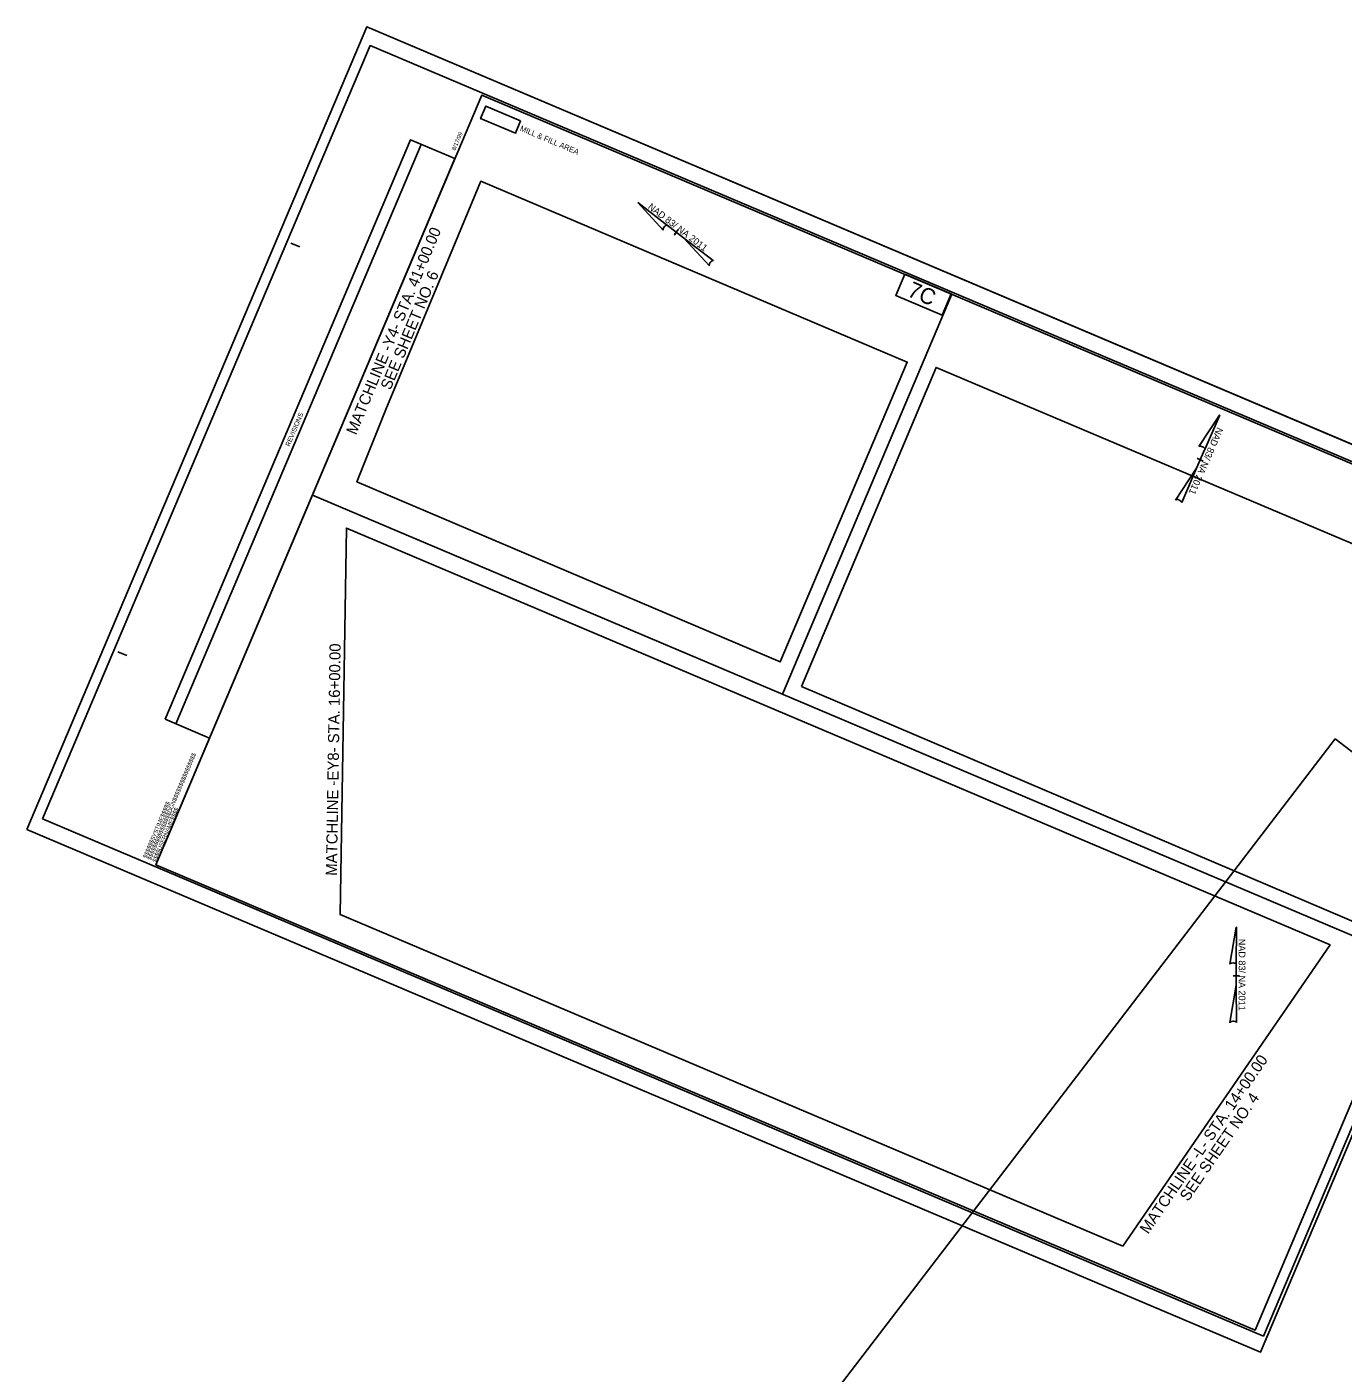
# Model space of a CAD drawing. Extents: x 1616919 to 1619754, y 897646 to 900286.
# Drawn here: x 1616919 to 1618573, y 898594 to 900286 of the extents above; entities that cross this region are included whole.
import ezdxf

# ---------------------------------------------------------------- set-up
doc = ezdxf.new("R2010")
doc.units = 0
for name, color, linetype in [('Exist DTM Breakline', 7, 'Continuous'), ('Exist DTM Breakline Underwater Cogo Number', 7, 'Continuous'), ('Exist DTM Breakline Underwater Cogo Point CELL', 7, 'Continuous'), ('Exist DTM Crownline', 7, 'Continuous'), ('Exist DTM Crownline Cogo Elevation', 7, 'Continuous'), ('Exist DTM Crownline Cogo Number', 7, 'Continuous'), ('Exist DTM Crownline Cogo Point CELL', 7, 'Continuous'), ('Exist DTM Regular Point CELL', 7, 'Continuous'), ('Exist DTM Top of Rail Cogo Number', 7, 'Continuous'), ('Exist DTM Top of Rail Cogo Point CELL', 7, 'Continuous'), ('Exist Railroads Signal Milepost CELL', 7, 'Continuous'), ('Exist Railroads Signal Milepost Cogo Elevation', 7, 'Continuous'), ('Exist Roads Curbs Cogo Point CELL', 7, 'Continuous'), ('Exist Roads EOP', 7, 'Continuous'), ('Exist Roads EOP Cogo Elevation', 7, 'Continuous'), ('Exist Roads EOT Cogo Number', 7, 'Continuous')]:
    doc.layers.add(name, color=color, linetype=linetype)

msp = doc.modelspace()

# ---------------------------------------------------------------- linework, layer by layer
at = {"layer": 'Exist DTM Breakline'}
msp.add_line((1617081, 899233), (1617081, 899233), dxfattribs=at)
at = {"layer": 'Exist DTM Breakline Underwater Cogo Number'}
msp.add_lwpolyline([(1618080.5, 899950), (1618022, 899974.8), (1618010.7, 899948.1), (1618069.2, 899923.3)], close=True, dxfattribs=at)
at = {"layer": 'Exist DTM Breakline Underwater Cogo Point CELL'}
for p, q in [((1617686.7, 900064.9), (1617686.6, 900064.9)), ((1617686.7, 900064.9), (1617686.6, 900064.9)), ((1617718.4, 900030.1), (1617686.6, 900064.9)), ((1617686.7, 900064.9), (1617724.5, 900035.8)), ((1617744.2, 900020.6), (1617723.4, 900036.6)), ((1617724.5, 900035.8), (1617723.5, 900036.6)), ((1617732.6, 900024.5), (1617732.5, 900024.5)), ((1617732.6, 900024.6), (1617737.5, 900030.9)), ((1617734.7, 900027.3), (1617732.6, 900024.5)), ((1617744.2, 900020.6), (1617776.5, 899985.2)), ((1617781.5, 899992), (1617744.2, 900020.6)), ((1618391.7, 899758.4), (1618417.7, 899797.7)), ((1618417.8, 899797.6), (1618398.7, 899753.8)), ((1618417.8, 899797.6), (1618417.7, 899797.7)), ((1618417.8, 899797.6), (1618417.7, 899797.7)), ((1618388.8, 899731.1), (1618399.3, 899755.1)), ((1618398.7, 899753.8), (1618399.2, 899755.1)), ((1618388.8, 899731.1), (1618362.3, 899691.1)), ((1618370.1, 899687.9), (1618388.8, 899731.1)), ((1618389.8, 899743.3), (1618389.7, 899743.3)), ((1618389.8, 899743.3), (1618397.1, 899740.1)), ((1618393, 899741.9), (1618389.8, 899743.3)), ((1618430.5, 899108.1), (1618438.7, 899154.4)), ((1618438.8, 899154.4), (1618438.7, 899154.4)), ((1618438.8, 899154.4), (1618438.7, 899154.4)), ((1618438.8, 899154.4), (1618438.7, 899106.6)), ((1618438.7, 899081.8), (1618438.7, 899108)), ((1618438.7, 899106.6), (1618438.7, 899108)), ((1618438.3, 899093.4), (1618434.7, 899093.4)), ((1618434.7, 899093.4), (1618434.7, 899093.4)), ((1618434.8, 899093.4), (1618442.8, 899093.4)), ((1618438.7, 899081.8), (1618430.4, 899034.6)), ((1618438.8, 899034.8), (1618438.7, 899081.8))]:
    msp.add_line(p, q, dxfattribs=at)
for centre, major_axis, start_param, end_param in [((1617721.3, 900033.1), (2.6, 3.33), 0.216388, 2.908219), ((1617779.3, 899988.5), (2.6, 3.33), 0.201328, 3.141593), ((1618395.3, 899756.3), (3.87, -1.72), 0.216388, 2.908219), ((1618366.1, 899689.3), (3.87, -1.72), 0.201328, 3.141593), ((1618434.6, 899107.6), (4.23, -0.03), 0.216388, 2.908219), ((1618434.6, 899034.4), (4.23, -0.03), 0.201328, 3.141593)]:
    msp.add_ellipse(centre, major_axis=major_axis, ratio=0.461098, start_param=start_param, end_param=end_param, dxfattribs=at)
at = {"layer": 'Exist DTM Crownline'}
msp.add_lwpolyline([(1617276, 899693.4), (1617090.8, 899256.1)], dxfattribs=at)
at = {"layer": 'Exist DTM Crownline Cogo Elevation'}
for p, q in [((1617346, 900285.5), (1616918.9, 899277.3)), ((1618896.2, 899628.9), (1617346, 900285.5)), ((1616918.9, 899277.3), (1618469.1, 898620.7))]:
    msp.add_line(p, q, dxfattribs=at)
at = {"layer": 'Exist DTM Crownline Cogo Number'}
msp.add_lwpolyline([(1618562.8, 899391.2), (1617924.4, 898557.6), (1619115.3, 897645.5), (1619625.1, 898311.3), (1619435.2, 898456.7), (1619563.8, 898624.6)], close=True, dxfattribs=at)
at = {"layer": 'Exist DTM Crownline Cogo Point CELL'}
msp.add_lwpolyline([(1616938.7, 899290.6), (1618472.8, 898640.8), (1618884.2, 899612.3), (1617350.2, 900262.1)], close=True, dxfattribs=at)
at = {"layer": 'Exist DTM Top of Rail Cogo Number'}
msp.add_lwpolyline([(1617539.3, 900167.5), (1617495.7, 900186), (1617489.1, 900170.4), (1617532.7, 900151.9)], close=True, dxfattribs=at)
at = {"layer": 'Exist DTM Top of Rail Cogo Point CELL'}
msp.add_lwpolyline([(1617539.3, 900167.5), (1617495.7, 900186), (1617489.1, 900170.4), (1617532.7, 900151.9), (1617539.3, 900167.5)], dxfattribs=at)
at = {"layer": 'Exist Railroads Signal Milepost CELL'}
for points in [[(1617369.9, 899804.7), (1617485.1, 900081.8), (1617489.3, 900091.7), (1618025.1, 899864.5), (1617865.6, 899487.7), (1617333.7, 899713.8)], [(1617892.5, 899456.8), (1618061.5, 899857.8), (1618651.5, 899607.9), (1618606.1, 899500.6), (1618729.7, 899448.3), (1618721, 899429.2), (1618597.1, 899156.7)], [(1618296.3, 898753.8), (1617312.4, 899170.5), (1617320.4, 899655.8), (1618556.6, 899132.2)]]:
    msp.add_lwpolyline(points, close=True, dxfattribs=at)
at = {"layer": 'Exist Railroads Signal Milepost Cogo Elevation'}
msp.add_line((1617106, 899410), (1617414.4, 900138), dxfattribs=at)
msp.add_lwpolyline([(1617092.6, 899415.7), (1617401, 900143.7), (1617456.7, 900120.1), (1617148.4, 899392)], close=True, dxfattribs=at)
at = {"layer": 'Exist Roads EOP'}
for p, q in [((1617250.5, 900014), (1617262, 900009.1)), ((1617033, 899500.4), (1617044.5, 899495.6)), ((1617081, 899233), (1617081, 899233))]:
    msp.add_line(p, q, dxfattribs=at)
msp.add_lwpolyline([(1618871.8, 899614.8), (1617490.5, 900199.9), (1617081, 899233), (1618462.2, 898648)], close=True, dxfattribs=at)
at = {"layer": 'Exist Roads EOP Cogo Elevation'}
msp.add_lwpolyline([(1616918.9, 899277.3), (1618469.1, 898620.7), (1618896.2, 899628.9), (1617346, 900285.5)], close=True, dxfattribs=at)
at = {"layer": 'Exist Roads EOT Cogo Number'}
for p, q in [((1617485.1, 900081.8), (1617369.9, 899804.7)), ((1617868.4, 899447.2), (1618081.3, 899949.7)), ((1617277.7, 899697.4), (1618658.9, 899112.3)), ((1617320.4, 899655.8), (1617312.4, 899170.5)), ((1618556.6, 899132.2), (1618296.3, 898753.8))]:
    msp.add_line(p, q, dxfattribs=at)

# ---------------------------------------------------------------- texts
at = {"layer": 'Exist DTM Breakline'}
for s, p in [('$$$$$$$$$$$$$$$$DGN$$$$$$$$$$$$$$$$', (1617074.9, 899238.2)), ('$$$$$$SYSTIME$$$$$', (1617069.3, 899240.6)), ('$$$$USERNAME$$$$', (1617081, 899235.6))]:
    msp.add_text(s, height=5.25, rotation=67.0441, dxfattribs=at).set_placement(p)
at = {"layer": 'Exist DTM Breakline Underwater Cogo Number'}
msp.add_text('7C', height=20, rotation=337.0346, dxfattribs=at).set_placement((1618024.2, 899947.9))
at = {"layer": 'Exist DTM Breakline Underwater Cogo Point CELL'}
for rotation, p in [(322.4156, (1617698.5, 900058.1)), (246.4674, (1618414.7, 899783.1)), (269.9808, (1618441.7, 899139.9))]:
    msp.add_text('NAD 83/ NA 2011', height=8.5, rotation=rotation, dxfattribs=at).set_placement(p)
at = {"layer": 'Exist DTM Regular Point CELL'}
for s, rotation, p in [('MATCHLINE -Y4- STA. 41+00.00', 67.4198, (1617332.5, 899772.1)), ('SEE SHEET NO. 6', 67.4198, (1617375.7, 899828.4)), ('MATCHLINE -EY8- STA. 16+00.00', 89.0571, (1617308.5, 899219)), ('MATCHLINE -L- STA. 14+00.00', 55.4794, (1618327.8, 898768.1)), ('SEE SHEET NO. 4', 55.4794, (1618378.1, 898809.1))]:
    msp.add_text(s, height=14, rotation=rotation, dxfattribs=at).set_placement(p)
at = {"layer": 'Exist Railroads Signal Milepost Cogo Elevation'}
msp.add_text('REVISIONS', height=6, rotation=67.0441, dxfattribs=at).set_placement((1617249, 899757.9))
at = {"layer": 'Exist Roads Curbs Cogo Point CELL'}
msp.add_text('MILL & FILL AREA', height=7, rotation=337.0441, dxfattribs=at).set_placement((1617537.9, 900155.5))
at = {"layer": 'Exist Roads EOP'}
msp.add_text('8/17/99', height=5.25, rotation=67.0441, dxfattribs=at).set_placement((1617457.3, 900129.8))

doc.saveas('drawing.dxf')
